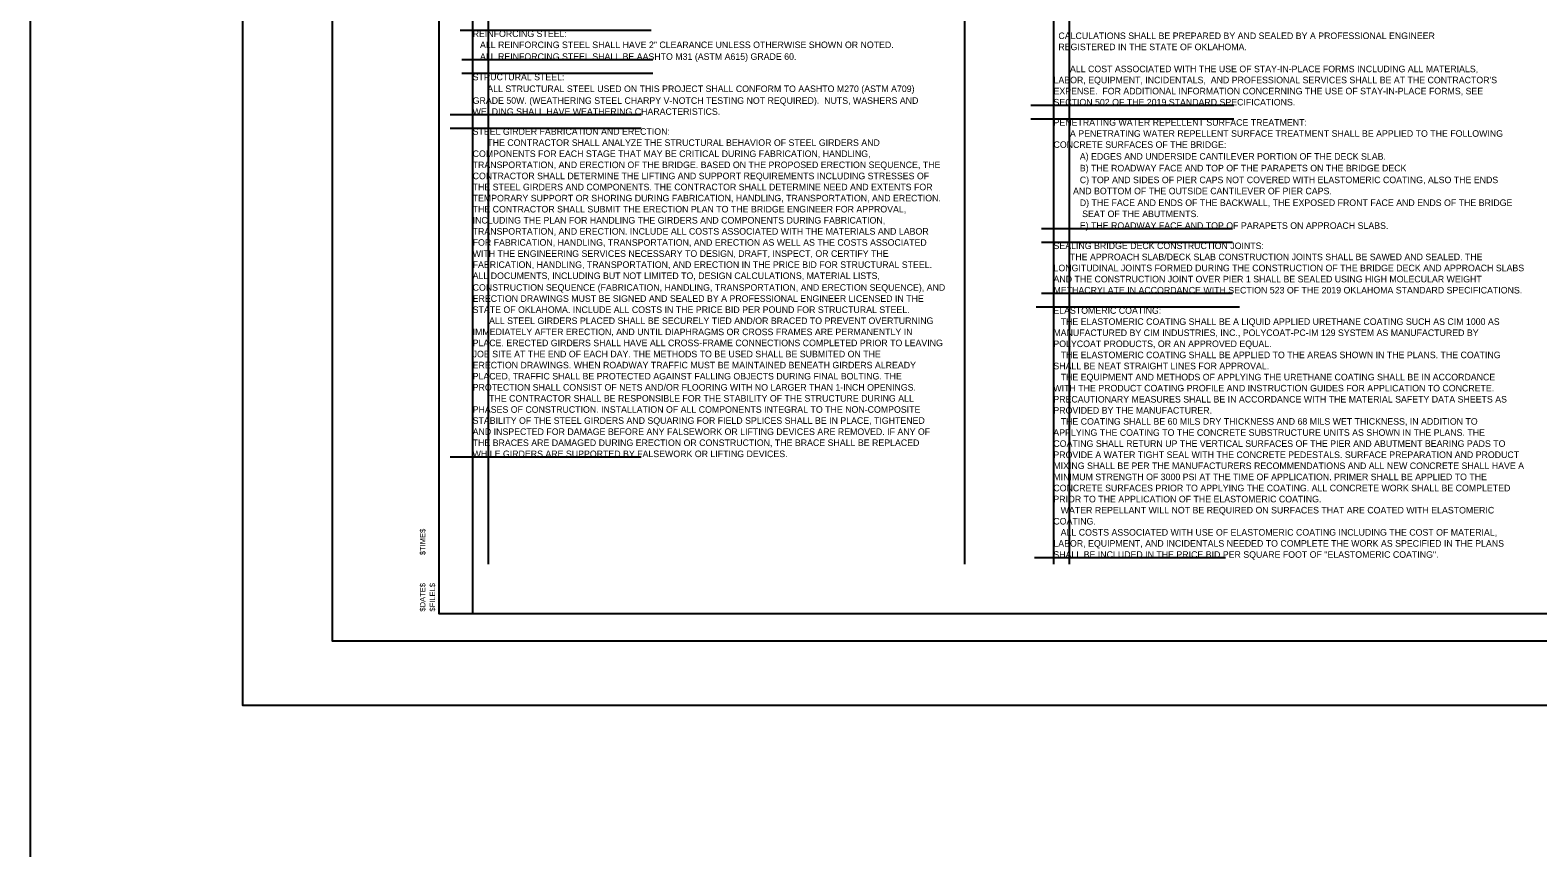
# Model space of a CAD drawing. Extents: x 12312.5 to 12355.9, y 579 to 640.5.
# Drawn here: x 12312.48 to 12340.01, y 610.44 to 625.38 of the extents above; entities that cross this region are included whole.
import ezdxf

# ---------------------------------------------------------------- set-up
doc = ezdxf.new("R2010")
doc.units = 0
for name, color, linetype in [('S', 7, 'Continuous'), ('SHT_Plot_Shape_Full', 7, 'Continuous'), ('SHT_Plot_Shape_Half', 7, 'Continuous'), ('SHT_Plot_Stamp', 7, 'Continuous'), ('SHT_Sheet_Border', 7, 'Continuous'), ('T', 7, 'Continuous')]:
    doc.layers.add(name, color=color, linetype=linetype)

# ---------------------------------------------------------------- blocks, each defined once
blk = doc.blocks.new('Stamp_Plot_Stamp')
at = {"layer": 'SHT_Plot_Stamp'}
for s, p in [('$TIME$', (8.01, 7.43)), ('$DATE$', (8.01, 2.56)), ('$FILEL$', (8.85, 2.56))]:
    blk.add_text(s, height=0.472, rotation=90, dxfattribs=at).set_placement(p)

msp = doc.modelspace()

# ---------------------------------------------------------------- linework, layer by layer
at = {"layer": 'Defpoints'}
for p, q in [((12320.557, 635.276), (12320.557, 614.717)), ((12320.841, 635.276), (12320.841, 615.626)), ((12329.542, 635.276), (12329.542, 615.626)), ((12331.165, 635.276), (12331.165, 615.626)), ((12331.45, 635.276), (12331.45, 615.626)), ((12323.819, 625.374), (12320.33, 625.374)), ((12323.848, 624.836), (12320.358, 624.836)), ((12323.848, 624.586), (12320.358, 624.586)), ((12334.242, 624.003), (12330.752, 624.003)), ((12334.458, 624.003), (12330.969, 624.003)), ((12323.633, 623.832), (12320.144, 623.832)), ((12334.242, 623.753), (12330.752, 623.753)), ((12334.458, 623.753), (12330.969, 623.753)), ((12323.633, 623.582), (12320.144, 623.582)), ((12334.436, 621.749), (12330.946, 621.749)), ((12334.436, 621.499), (12330.946, 621.499)), ((12334.436, 620.569), (12330.946, 620.569)), ((12334.34, 620.319), (12330.85, 620.319)), ((12334.436, 620.319), (12330.946, 620.319)), ((12334.562, 620.319), (12331.072, 620.319)), ((12323.633, 617.58), (12320.144, 617.58)), ((12334.307, 615.741), (12330.817, 615.741))]:
    msp.add_line(p, q, dxfattribs=at)
at = {"layer": 'S'}
msp.add_lwpolyline([(12355.912, 640.488), (12312.476, 640.488), (12312.476, 579.031), (12355.912, 579.031)], close=True, dxfattribs=at)
at = {"layer": 'SHT_Plot_Shape_Full'}
msp.add_lwpolyline([(12316.36, 637.042), (12352.36, 637.042), (12352.36, 613.042), (12316.36, 613.042)], close=True, dxfattribs=at)
at = {"layer": 'SHT_Plot_Shape_Half'}
msp.add_lwpolyline([(12317.998, 636.217), (12351.998, 636.217), (12351.998, 614.217), (12317.998, 614.217)], close=True, dxfattribs=at)
at = {"layer": 'SHT_Sheet_Border'}
msp.add_lwpolyline([(12351.448, 614.717), (12319.948, 614.717), (12319.948, 635.717), (12351.448, 635.717)], close=True, dxfattribs=at)

# ---------------------------------------------------------------- block references
at = {"layer": 'SHT_Plot_Stamp', "xscale": 0.21166666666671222, "yscale": 0.21166666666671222}
msp.add_blockref('Stamp_Plot_Stamp', (12317.998, 614.217), dxfattribs=at)

# ---------------------------------------------------------------- texts
at = {"layer": 'T'}
for s, p in [('REINFORCING STEEL:', (12320.557, 625.254)), ('  CALCULATIONS SHALL BE PREPARED BY AND SEALED BY A PROFESSIONAL ENGINEER', (12331.165, 625.216)), ('   ALL REINFORCING STEEL SHALL HAVE 2" CLEARANCE UNLESS OTHERWISE SHOWN OR NOTED.', (12320.557, 625.051)), ('  REGISTERED IN THE STATE OF OKLAHOMA.', (12331.165, 625.013)), ('   ALL REINFORCING STEEL SHALL BE AASHTO M31 (ASTM A615) GRADE 60.', (12320.557, 624.836)), ('STRUCTURAL STEEL:', (12320.557, 624.463)), ("LABOR, EQUIPMENT, INCIDENTALS,  AND PROFESSIONAL SERVICES SHALL BE AT THE CONTRACTOR'S ", (12331.165, 624.408)), ('ALL COST ASSOCIATED WITH THE USE OF STAY-IN-PLACE FORMS INCLUDING ALL MATERIALS, ', (12331.465, 624.611)), ('      ALL STRUCTURAL STEEL USED ON THIS PROJECT SHALL CONFORM TO AASHTO M270 (ASTM A709) ', (12320.557, 624.248)), ('EXPENSE.  FOR ADDITIONAL INFORMATION CONCERNING THE USE OF STAY-IN-PLACE FORMS, SEE ', (12331.165, 624.206)), ('WELDING SHALL HAVE WEATHERING CHARACTERISTICS.', (12320.557, 623.832)), ('GRADE 50W. (WEATHERING STEEL CHARPY V-NOTCH TESTING NOT REQUIRED).  NUTS, WASHERS AND ', (12320.557, 624.033)), ('SECTION 502 OF THE 2019 STANDARD SPECIFICATIONS.', (12331.165, 624.003)), ('PENETRATING WATER REPELLENT SURFACE TREATMENT:', (12331.165, 623.633)), ('STEEL GIRDER FABRICATION AND ERECTION:', (12320.557, 623.467)), ('      THE CONTRACTOR SHALL ANALYZE THE STRUCTURAL BEHAVIOR OF STEEL GIRDERS AND ', (12320.557, 623.264)), ('A PENETRATING WATER REPELLENT SURFACE TREATMENT SHALL BE APPLIED TO THE FOLLOWING ', (12331.465, 623.431)), ('COMPONENTS FOR EACH STAGE THAT MAY BE CRITICAL DURING FABRICATION, HANDLING, ', (12320.557, 623.062)), ('CONCRETE SURFACES OF THE BRIDGE:', (12331.165, 623.228)), ('A) EDGES AND UNDERSIDE CANTILEVER PORTION OF THE DECK SLAB.', (12331.645, 623.013)), ('TRANSPORTATION, AND ERECTION OF THE BRIDGE. BASED ON THE PROPOSED ERECTION SEQUENCE, THE ', (12320.557, 622.859)), ('B) THE ROADWAY FACE AND TOP OF THE PARAPETS ON THE BRIDGE DECK', (12331.645, 622.799)), ('THE STEEL GIRDERS AND COMPONENTS. THE CONTRACTOR SHALL DETERMINE NEED AND EXTENTS FOR ', (12320.557, 622.454)), ('CONTRACTOR SHALL DETERMINE THE LIFTING AND SUPPORT REQUIREMENTS INCLUDING STRESSES OF ', (12320.557, 622.656)), ('C) TOP AND SIDES OF PIER CAPS NOT COVERED WITH ELASTOMERIC COATING, ALSO THE ENDS ', (12331.645, 622.584)), ('TEMPORARY SUPPORT OR SHORING DURING FABRICATION, HANDLING, TRANSPORTATION, AND ERECTION. ', (12320.557, 622.251)), ('        AND BOTTOM OF THE OUTSIDE CANTILEVER OF PIER CAPS.', (12331.165, 622.381)), ('D) THE FACE AND ENDS OF THE BACKWALL, THE EXPOSED FRONT FACE AND ENDS OF THE BRIDGE    ', (12331.645, 622.167)), ('THE CONTRACTOR SHALL SUBMIT THE ERECTION PLAN TO THE BRIDGE ENGINEER FOR APPROVAL, ', (12320.557, 622.049)), ('     SEAT OF THE ABUTMENTS.', (12331.465, 621.964)), ('TRANSPORTATION, AND ERECTION. INCLUDE ALL COSTS ASSOCIATED WITH THE MATERIALS AND LABOR ', (12320.557, 621.644)), ('INCLUDING THE PLAN FOR HANDLING THE GIRDERS AND COMPONENTS DURING FABRICATION, ', (12320.557, 621.846)), ('E) THE ROADWAY FACE AND TOP OF PARAPETS ON APPROACH SLABS.', (12331.645, 621.749)), ('FOR FABRICATION, HANDLING, TRANSPORTATION, AND ERECTION AS WELL AS THE COSTS ASSOCIATED ', (12320.557, 621.441)), ('SEALING BRIDGE DECK CONSTRUCTION JOINTS:', (12331.165, 621.38)), ('WITH THE ENGINEERING SERVICES NECESSARY TO DESIGN, DRAFT, INSPECT, OR CERTIFY THE ', (12320.557, 621.238)), ('THE APPROACH SLAB/DECK SLAB CONSTRUCTION JOINTS SHALL BE SAWED AND SEALED. THE ', (12331.465, 621.177)), ('ALL DOCUMENTS, INCLUDING BUT NOT LIMITED TO, DESIGN CALCULATIONS, MATERIAL LISTS, ', (12320.557, 620.833)), ('FABRICATION, HANDLING, TRANSPORTATION, AND ERECTION IN THE PRICE BID FOR STRUCTURAL STEEL. ', (12320.557, 621.036)), ('AND THE CONSTRUCTION JOINT OVER PIER 1 SHALL BE SEALED USING HIGH MOLECULAR WEIGHT ', (12331.165, 620.772)), ('LONGITUDINAL JOINTS FORMED DURING THE CONSTRUCTION OF THE BRIDGE DECK AND APPROACH SLABS ', (12331.165, 620.975)), ('CONSTRUCTION SEQUENCE (FABRICATION, HANDLING, TRANSPORTATION, AND ERECTION SEQUENCE), AND ', (12320.557, 620.619)), ('METHACRYLATE IN ACCORDANCE WITH SECTION 523 OF THE 2019 OKLAHOMA STANDARD SPECIFICATIONS.', (12331.165, 620.569)), ('ERECTION DRAWINGS MUST BE SIGNED AND SEALED BY A PROFESSIONAL ENGINEER LICENSED IN THE ', (12320.557, 620.416)), ('STATE OF OKLAHOMA. INCLUDE ALL COSTS IN THE PRICE BID PER POUND FOR STRUCTURAL STEEL.', (12320.557, 620.213)), ('ALL STEEL GIRDERS PLACED SHALL BE SECURELY TIED AND/OR BRACED TO PREVENT OVERTURNING ', (12320.857, 620.011)), ('ELASTOMERIC COATING:', (12331.162, 620.198)), ('   THE ELASTOMERIC COATING SHALL BE A LIQUID APPLIED URETHANE COATING SUCH AS CIM 1000 AS ', (12331.162, 619.995)), ('IMMEDIATELY AFTER ERECTION, AND UNTIL DIAPHRAGMS OR CROSS FRAMES ARE PERMANENTLY IN ', (12320.557, 619.808)), ('MANUFACTURED BY CIM INDUSTRIES, INC., POLYCOAT-PC-IM 129 SYSTEM AS MANUFACTURED BY ', (12331.162, 619.792)), ('JOB SITE AT THE END OF EACH DAY. THE METHODS TO BE USED SHALL BE SUBMITED ON THE ', (12320.557, 619.403)), ('PLACE. ERECTED GIRDERS SHALL HAVE ALL CROSS-FRAME CONNECTIONS COMPLETED PRIOR TO LEAVING ', (12320.557, 619.606)), ('POLYCOAT PRODUCTS, OR AN APPROVED EQUAL.', (12331.162, 619.59)), ('ERECTION DRAWINGS. WHEN ROADWAY TRAFFIC MUST BE MAINTAINED BENEATH GIRDERS ALREADY ', (12320.557, 619.201)), ('SHALL BE NEAT STRAIGHT LINES FOR APPROVAL.', (12331.162, 619.185)), ('   THE ELASTOMERIC COATING SHALL BE APPLIED TO THE AREAS SHOWN IN THE PLANS. THE COATING ', (12331.162, 619.387)), ('PLACED, TRAFFIC SHALL BE PROTECTED AGAINST FALLING OBJECTS DURING FINAL BOLTING. THE ', (12320.557, 618.998)), ('   THE EQUIPMENT AND METHODS OF APPLYING THE URETHANE COATING SHALL BE IN ACCORDANCE ', (12331.162, 618.982)), ('PROTECTION SHALL CONSIST OF NETS AND/OR FLOORING WITH NO LARGER THAN 1-INCH OPENINGS. ', (12320.557, 618.795)), ('THE CONTRACTOR SHALL BE RESPONSIBLE FOR THE STABILITY OF THE STRUCTURE DURING ALL ', (12320.857, 618.593)), ('WITH THE PRODUCT COATING PROFILE AND INSTRUCTION GUIDES FOR APPLICATION TO CONCRETE. ', (12331.162, 618.78)), ('PRECAUTIONARY MEASURES SHALL BE IN ACCORDANCE WITH THE MATERIAL SAFETY DATA SHEETS AS ', (12331.162, 618.577)), ('PHASES OF CONSTRUCTION. INSTALLATION OF ALL COMPONENTS INTEGRAL TO THE NON-COMPOSITE ', (12320.557, 618.39)), ('PROVIDED BY THE MANUFACTURER.', (12331.162, 618.374)), ('STABILITY OF THE STEEL GIRDERS AND SQUARING FOR FIELD SPLICES SHALL BE IN PLACE, TIGHTENED ', (12320.557, 618.188)), ('   THE COATING SHALL BE 60 MILS DRY THICKNESS AND 68 MILS WET THICKNESS, IN ADDITION TO ', (12331.162, 618.172)), ('AND INSPECTED FOR DAMAGE BEFORE ANY FALSEWORK OR LIFTING DEVICES ARE REMOVED. IF ANY OF ', (12320.557, 617.985)), ('THE BRACES ARE DAMAGED DURING ERECTION OR CONSTRUCTION, THE BRACE SHALL BE REPLACED ', (12320.557, 617.783)), ('APPLYING THE COATING TO THE CONCRETE SUBSTRUCTURE UNITS AS SHOWN IN THE PLANS. THE ', (12331.162, 617.969)), ('COATING SHALL RETURN UP THE VERTICAL SURFACES OF THE PIER AND ABUTMENT BEARING PADS TO ', (12331.162, 617.767)), ('WHILE GIRDERS ARE SUPPORTED BY FALSEWORK OR LIFTING DEVICES.', (12320.557, 617.58)), ('PROVIDE A WATER TIGHT SEAL WITH THE CONCRETE PEDESTALS. SURFACE PREPARATION AND PRODUCT ', (12331.162, 617.564)), ('MIXING SHALL BE PER THE MANUFACTURERS RECOMMENDATIONS AND ALL NEW CONCRETE SHALL HAVE A ', (12331.162, 617.362)), ('CONCRETE SURFACES PRIOR TO APPLYING THE COATING. ALL CONCRETE WORK SHALL BE COMPLETED ', (12331.162, 616.956)), ('MINIMUM STRENGTH OF 3000 PSI AT THE TIME OF APPLICATION. PRIMER SHALL BE APPLIED TO THE ', (12331.162, 617.159)), ('PRIOR TO THE APPLICATION OF THE ELASTOMERIC COATING.', (12331.162, 616.754)), ('   WATER REPELLANT WILL NOT BE REQUIRED ON SURFACES THAT ARE COATED WITH ELASTOMERIC ', (12331.162, 616.551)), ('COATING.', (12331.162, 616.349)), ('   ALL COSTS ASSOCIATED WITH USE OF ELASTOMERIC COATING INCLUDING THE COST OF MATERIAL, ', (12331.162, 616.146)), ('LABOR, EQUIPMENT, AND INCIDENTALS NEEDED TO COMPLETE THE WORK AS SPECIFIED IN THE PLANS ', (12331.162, 615.944)), ('SHALL BE INCLUDED IN THE PRICE BID PER SQUARE FOOT OF "ELASTOMERIC COATING".', (12331.162, 615.741))]:
    msp.add_text(s, height=0.12, dxfattribs=at).set_placement(p)

doc.saveas('drawing.dxf')
